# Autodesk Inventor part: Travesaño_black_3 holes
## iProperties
Created: 2008-01
Part Number: Travesaño_black_3 holes
Document SubType Name: Modeling
Designer: eruiz-tagle
Mass: 0.310726 g
Surface Area: 6.9621 cm^2
Volume: 0.310726 cm^3
Density: 1 g/cm^3
Author: eruiz-tagle
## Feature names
1. Extrusion1
2. Fillet1
3. Fillet2
4. Hole1
5. Extrusion2
6. Fillet3
7. Mirror1
8. Hole2
9. Mirror2
